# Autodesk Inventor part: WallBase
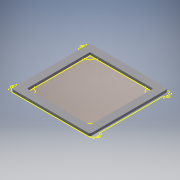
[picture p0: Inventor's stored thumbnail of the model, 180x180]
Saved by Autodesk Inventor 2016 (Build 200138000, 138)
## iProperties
Created: 2015-11
Part Number: WallBase
Material: Generic
Document SubType Name: Modeling
Designer: John
Density: 1 g/cm^3
Appearance: Default
Author: John
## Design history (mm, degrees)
workplane "Work Plane1"
sketch "Sketch3"
  geometry: L1 (3.125, 169.575)-(3.125, 3.125) reference; L2 (169.575, 169.575)-(3.125, 169.575) reference; L3 (169.575, 3.125)-(169.575, 169.575) reference; L4 (3.125, 3.125)-(169.575, 3.125) reference; L5 (171.825, 0.875)-(171.825, 171.825); L6 (171.825, 171.825)-(0.875, 171.825); L7 (0.875, 171.825)-(0.875, 0.875); L8 (0.875, 0.875)-(171.825, 0.875); L9 (189.825, -17.125)-(189.825, 189.825); L10 (189.825, 189.825)-(-17.125, 189.825); L11 (-17.125, 189.825)-(-17.125, -17.125); L12 (-17.125, -17.125)-(189.825, -17.125); 1 further point
  constraints: 16 end point, 6 other
  dimensions: "d6" = 2.25 distance between parallel lines of L4 L8; "d7" = 18 distance between parallel lines of L8 L12
extrude "Extrusion2" new body sketch "Sketch3" distance "d8" = 6.35; taper "d9" = 0 deg
fillet "Fillet3" dims "d10" = 3.175
fillet "Fillet4" dims "d11" = 5
sketch "Sketch4"
  geometry: L1 (-17.125, 184.825)-(-17.125, -12.125) reference; L2 (-12.125, -17.125)-(184.825, -17.125) reference; L3 (189.825, -12.125)-(189.825, 184.825) reference; L4 (184.825, 189.825)-(-12.125, 189.825) reference; L5 (168.65, 0.875)-(4.05, 0.875) reference; L6 (0.875, 4.05)-(0.875, 168.65) reference; L7 (4.05, 171.825)-(168.65, 171.825) reference; L8 (171.825, 168.65)-(171.825, 4.05) reference; L9 (175, -2.3)-(-2.3, -2.3); L10 (-2.3, -2.3)-(-2.3, 175); L11 (-2.3, 175)-(175, 175); L12 (175, 175)-(175, -2.3); L13 (-5.8, -5.8)-(178.5, -5.8); L14 (178.5, -5.8)-(178.5, 178.5); L15 (178.5, 178.5)-(-5.8, 178.5); L16 (-5.8, 178.5)-(-5.8, -5.8); A1 r 5 centre (-12.125, 184.825) between (-12.125, 189.825) and (-17.125, 184.825) reference; A2 r 5 centre (-12.125, -12.125) between (-17.125, -12.125) and (-12.125, -17.125) reference; A3 r 5 centre (184.825, -12.125) between (184.825, -17.125) and (189.825, -12.125) reference; A4 r 5 centre (184.825, 184.825) between (189.825, 184.825) and (184.825, 189.825) reference; A5 r 3.175 centre (4.05, 4.05) between (0.875, 4.05) and (4.05, 0.875) reference; A6 r 3.175 centre (4.05, 168.65) between (4.05, 171.825) and (0.875, 168.65) reference; A7 r 3.175 centre (168.65, 168.65) between (171.825, 168.65) and (168.65, 171.825) reference; A8 r 3.175 centre (168.65, 4.05) between (168.65, 0.875) and (171.825, 4.05) reference; 1 further point
  constraints: 16 end point, 4 parallel, 2 perpendicular, 1 horizontal, 3 other
  dimensions: "d12" = 3.175 distance between parallel lines of L5 L9; "d13" = 3.175 distance between parallel lines of L6 L10 (= d12); "d14" = 3.175 distance between parallel lines of L7 L11 (= d13); "d15" = 3.175 distance between parallel lines of L8 L12 (= d13); "d16" = 3.5 distance between parallel lines of L9 L13
extrude "Extrusion3" cut sketch "Sketch4" distance "d17" = 3.175; taper "d18" = 0 deg
sketch "Sketch5"
  geometry: L1 (188.018, -17.5)-(-15.318, -17.5) reference; L2 (192.7, 5)-(192.7, 167.7) reference; L3 (-15.318, 190.2)-(188.018, 190.2) reference; L4 (-20, 5)-(-20, 167.7) reference; L5 (-1.875, 23.333)-(-1.875, 26.33) reference; L6 (-4.909, 26.33)-(-1.875, 26.33) reference; L7 (-1.875, 26.834)-(-4.908, 26.834) reference; L8 (-1.875, 26.834)-(-1.875, 41.272) reference; L9 (-1.875, 41.272)-(-6.918, 41.272) reference; L10 (-6.918, 41.772)-(-1.875, 41.772) reference; L11 (-1.875, 41.772)-(-1.875, 56.214) reference; L12 (-1.875, 56.214)-(-4.908, 56.214) reference; L13 (-4.909, 56.718)-(-1.875, 56.718) reference; L14 (-1.875, 56.718)-(-1.875, 71.156) reference; L15 (-1.875, 71.156)-(-6.918, 71.156) reference; L16 (-6.919, 71.66)-(-1.875, 71.66) reference; L17 (-1.875, 71.66)-(-1.875, 86.098) reference; L18 (-4.909, 86.098)-(-1.875, 86.098) reference; L19 (-1.875, 86.598)-(-4.908, 86.598) reference; L20 (-1.875, 86.598)-(-1.875, 101.04) reference; L21 (-1.875, 101.04)-(-6.918, 101.04) reference; L22 (-6.919, 101.544)-(-1.875, 101.544) reference; L23 (-1.875, 101.544)-(-1.875, 115.982) reference; L24 (-4.909, 115.982)-(-1.875, 115.982) reference; L25 (-1.875, 116.486)-(-4.908, 116.486) reference; L26 (-1.875, 116.486)-(-1.875, 130.924) reference; L27 (-6.919, 130.924)-(-1.875, 130.924) reference; L28 (-1.875, 131.424)-(-6.917, 131.424) reference; L29 (-1.875, 131.424)-(-1.875, 145.866) reference; L30 (-4.909, 145.866)-(-1.875, 145.866) reference; L31 (-1.875, 146.37)-(-4.908, 146.37) reference; L32 (-1.875, 146.37)-(-1.875, 149.367) reference; L33 (23.333, 174.575)-(26.334, 174.575) reference; L34 (26.334, 174.575)-(26.334, 177.608) reference; L35 (26.834, 177.608)-(26.834, 174.575) reference; L36 (26.834, 174.575)-(41.276, 174.575) reference; L37 (41.276, 174.575)-(41.276, 179.618) reference; L38 (41.776, 179.618)-(41.776, 174.575) reference; L39 (41.776, 174.575)-(56.218, 174.575) reference; L40 (56.218, 174.575)-(56.218, 177.608) reference; L41 (56.718, 177.608)-(56.718, 174.575) reference; L42 (56.718, 174.575)-(71.16, 174.575) reference; L43 (71.16, 174.575)-(71.16, 179.618) reference; L44 (71.66, 179.618)-(71.66, 174.575) reference; L45 (71.66, 174.575)-(86.102, 174.575) reference; L46 (86.102, 174.575)-(86.102, 177.608) reference; L47 (86.602, 177.608)-(86.602, 174.575) reference; L48 (86.602, 174.575)-(101.044, 174.575) reference; L49 (101.044, 174.575)-(101.044, 179.618) reference; L50 (101.544, 179.618)-(101.544, 174.575) reference; L51 (101.544, 174.575)-(115.986, 174.575) reference; L52 (115.986, 174.575)-(115.986, 177.608) reference; L53 (116.486, 177.608)-(116.486, 174.575) reference; L54 (116.486, 174.575)-(130.928, 174.575) reference; L55 (130.928, 174.575)-(130.928, 179.618) reference; L56 (131.428, 179.618)-(131.428, 174.575) reference; L57 (131.428, 174.575)-(145.87, 174.575) reference; L58 (145.87, 174.575)-(145.87, 177.608) reference; L59 (146.37, 177.608)-(146.37, 174.575) reference; L60 (146.37, 174.575)-(149.367, 174.575) reference; L61 (174.575, 149.367)-(174.575, 146.366) reference; L62 (174.575, 146.366)-(177.608, 146.366) reference; L63 (177.608, 145.87)-(174.575, 145.87) reference; L64 (174.575, 145.87)-(174.575, 131.428) reference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; C1 r 3.75 at (161.062, -8.65) reference; C2 r 3.75 at (161.062, 181.35) reference; C3 r 3.75 at (-8.65, 161.058) reference; C4 r 3.75 at (11.642, -8.65) reference; C5 r 3.75 at (-8.65, 11.642) reference; C6 r 3.75 at (11.642, 181.35) reference; C7 r 3.75 at (181.35, 161.058) reference; C8 r 3.75 at (181.35, 11.642) reference; C9 r 1.75 at (197.7, -5) reference; C10 r 1.75 at (197.7, 177.7) reference; C11 r 1.75 at (-25, 177.7) reference; C12 r 1.75 at (-25, -5) reference; C13 r 1.75 at (-8.3, -8.3) reference; C14 r 1.75 at (181, -8.3) reference; C15 r 1.75 at (181, 181) reference; C16 r 1.75 at (-8.3, 181) reference; C17 r 1.75 at (181, 181); C18 r 1.75 at (181.35, 161.058); C19 r 1.75 at (181.35, 146.12); C20 r 1.75 at (181.35, 116.236); C21 r 1.75 at (181.35, 86.352); C22 r 1.75 at (181.35, 56.464); C23 r 1.75 at (181.35, 26.584); C24 r 1.75 at (181.35, 11.642); C25 r 1.75 at (181, -8.3); A1 r 5 centre (-15.318, -12.5) between (-20.159, -13.75) and (-15.318, -17.5) reference; A2 r 5 centre (188.018, -12.5) between (188.018, -17.5) and (192.859, -13.75) reference; A3 r 5 centre (197.7, -15) between (197.7, -10) and (192.859, -13.75) reference; A4 r 5 centre (197.7, -5) between (197.7, -10) and (197.7, 0) reference; A5 r 5 centre (197.7, 5) between (192.7, 5) and (197.7, 0) reference; A6 r 5 centre (197.7, 167.7) between (197.7, 172.7) and (192.7, 167.7) reference; A7 r 5 centre (197.7, 177.7) between (197.7, 172.7) and (197.7, 182.7) reference; A8 r 5 centre (197.7, 187.7) between (192.859, 186.45) and (197.7, 182.7) reference; A9 r 5 centre (188.018, 185.2) between (192.859, 186.45) and (188.018, 190.2) reference; A10 r 5 centre (-15.318, 185.2) between (-15.318, 190.2) and (-20.159, 186.45) reference; A11 r 5 centre (-25, 187.7) between (-25, 182.7) and (-20.159, 186.45) reference; A12 r 5 centre (-25, 177.7) between (-25, 182.7) and (-25, 172.7) reference; A13 r 5 centre (-25, 167.7) between (-20, 167.7) and (-25, 172.7) reference; A14 r 5 centre (-25, 5) between (-25, 0) and (-20, 5) reference; A15 r 5 centre (-25, -5) between (-25, 0) and (-25, -10) reference; A16 r 5 centre (-25, -15) between (-20.159, -13.75) and (-25, -10) reference; A17 r 3.75 centre (-8.65, 26.584) between (-4.908, 26.834) and (-4.909, 26.33) reference; A18 r 1.75 centre (-8.65, 41.522) between (-6.918, 41.772) and (-6.918, 41.272) reference; A19 r 3.75 centre (-8.65, 56.464) between (-4.909, 56.718) and (-4.908, 56.214) reference; A20 r 1.75 centre (-8.65, 71.406) between (-6.919, 71.66) and (-6.918, 71.156) reference; A21 r 3.75 centre (-8.65, 86.352) between (-4.908, 86.598) and (-4.909, 86.098) reference; A22 r 1.75 centre (-8.65, 101.29) between (-6.919, 101.544) and (-6.918, 101.04) reference; A23 r 3.75 centre (-8.65, 116.236) between (-4.908, 116.486) and (-4.909, 115.982) reference; A24 r 1.75 centre (-8.65, 131.178) between (-6.917, 131.424) and (-6.919, 130.924) reference; A25 r 3.75 centre (-8.65, 146.12) between (-4.908, 146.37) and (-4.909, 145.866) reference; A26 r 5 centre (3.125, 149.367) between (3.634, 154.341) and (-1.875, 149.367) reference; A27 r 13.428 centre (5, 167.7) between (3.634, 154.341) and (18.359, 169.066) reference; A28 r 5 centre (23.333, 169.575) between (23.333, 174.575) and (18.359, 169.066) reference; A29 r 3.75 centre (26.584, 181.35) between (26.834, 177.608) and (26.334, 177.608) reference; A30 r 1.75 centre (41.526, 181.35) between (41.776, 179.618) and (41.276, 179.618) reference; A31 r 3.75 centre (56.468, 181.35) between (56.718, 177.608) and (56.218, 177.608) reference; A32 r 1.75 centre (71.41, 181.35) between (71.66, 179.618) and (71.16, 179.618) reference; A33 r 3.75 centre (86.352, 181.35) between (86.602, 177.608) and (86.102, 177.608) reference; A34 r 1.75 centre (101.294, 181.35) between (101.544, 179.618) and (101.044, 179.618) reference; A35 r 3.75 centre (116.236, 181.35) between (116.486, 177.608) and (115.986, 177.608) reference; A36 r 1.75 centre (131.178, 181.35) between (131.428, 179.618) and (130.928, 179.618) reference; A37 r 3.75 centre (146.12, 181.35) between (146.37, 177.608) and (145.87, 177.608) reference; A38 r 5 centre (149.367, 169.575) between (154.341, 169.066) and (149.367, 174.575) reference; A39 r 13.428 centre (167.7, 167.7) between (154.341, 169.066) and (169.066, 154.341) reference; A40 r 5 centre (169.575, 149.367) between (174.575, 149.367) and (169.066, 154.341) reference; A41 r 3.75 centre (181.35, 146.12) between (177.608, 145.87) and (177.608, 146.366) reference; A42 r 1.75 centre (181.35, 131.178) between (179.618, 130.928) and (179.618, 131.428) reference; A43 r 3.75 centre (181.35, 116.236) between (177.608, 115.986) and (177.608, 116.482) reference; A44 r 1.75 centre (181.35, 101.294) between (179.619, 101.04) and (179.617, 101.54) reference; A45 r 3.75 centre (181.35, 86.352) between (177.609, 86.098) and (177.608, 86.602) reference; A46 r 1.75 centre (181.35, 71.406) between (179.618, 71.156) and (179.619, 71.66) reference; A47 r 3.75 centre (181.35, 56.464) between (177.608, 56.214) and (177.609, 56.718) reference; A48 r 1.75 centre (181.35, 41.526) between (179.618, 41.276) and (179.618, 41.776) reference; A49 r 3.75 centre (181.35, 26.584) between (177.609, 26.33) and (177.608, 26.834) reference; A50 r 5 centre (169.575, 23.333) between (169.066, 18.359) and (174.575, 23.333) reference; A51 r 13.428 centre (167.7, 5) between (169.066, 18.359) and (154.341, 3.634) reference; A52 r 5 centre (149.367, 3.125) between (149.367, -1.875) and (154.341, 3.634) reference; A53 r 3.75 centre (146.12, -8.65) between (145.87, -4.908) and (146.37, -4.908) reference; A54 r 1.75 centre (131.178, -8.65) between (130.928, -6.918) and (131.428, -6.918) reference; A55 r 3.75 centre (116.236, -8.65) between (115.986, -4.908) and (116.486, -4.908) reference; A56 r 1.75 centre (101.294, -8.65) between (101.044, -6.918) and (101.544, -6.918) reference; A57 r 3.75 centre (86.352, -8.65) between (86.102, -4.908) and (86.602, -4.908) reference; A58 r 1.75 centre (71.41, -8.65) between (71.16, -6.918) and (71.66, -6.918) reference; A59 r 3.75 centre (56.468, -8.65) between (56.218, -4.908) and (56.718, -4.908) reference; A60 r 1.75 centre (41.526, -8.65) between (41.276, -6.918) and (41.776, -6.918) reference; A61 r 3.75 centre (26.584, -8.65) between (26.334, -4.908) and (26.834, -4.908) reference; A62 r 5 centre (23.333, 3.125) between (18.359, 3.634) and (23.333, -1.875) reference; A63 r 13.428 centre (5, 5) between (18.359, 3.634) and (3.634, 18.359) reference; A64 r 5 centre (3.125, 23.333) between (-1.875, 23.333) and (3.634, 18.359) reference; 5 further points
  constraints: 13 coincident, 9 centre point, 9 equal radius, 12 other
extrude "Extrusion4" cut sketch "Sketch5" stored distance "d19" = 3.175; taper "d20" = 0 deg
workaxis "Work Axis1"
  workplane "Work Plane2"
  workplane "Work Plane3"
pattern_circular "Circular Pattern1" dims angle "d22" = 360 deg
body "Solid2"
node "Reference3"
node "Projected Loop1"
node "Reference4"
